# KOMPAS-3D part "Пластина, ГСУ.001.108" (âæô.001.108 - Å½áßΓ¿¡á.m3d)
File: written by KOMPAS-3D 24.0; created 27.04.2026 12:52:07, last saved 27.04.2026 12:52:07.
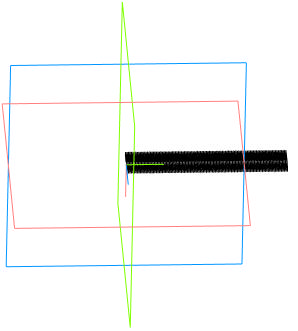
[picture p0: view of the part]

Document properties: Автор: User7; Полное имя файла: C:\Users\User7\Desktop\олимп\ГСУ.001.108 - Пластина.m3d

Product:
- Part/product: Пластина  | designation ГСУ.001.108
    Масса: 0.000055

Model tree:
1. Эскиз:1
2. Элемент выдавливания:1
     Расстояние 1 = 0.01
3. Массив по сетке:1  (with: Элемент выдавливания:1, Эскиз:1, Ребро.Элемент выдавливания:1)  (110 pattern instances)
     Шаг 1 = 0.311818; Угол раствора = 90

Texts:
  ГСУ.001.108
